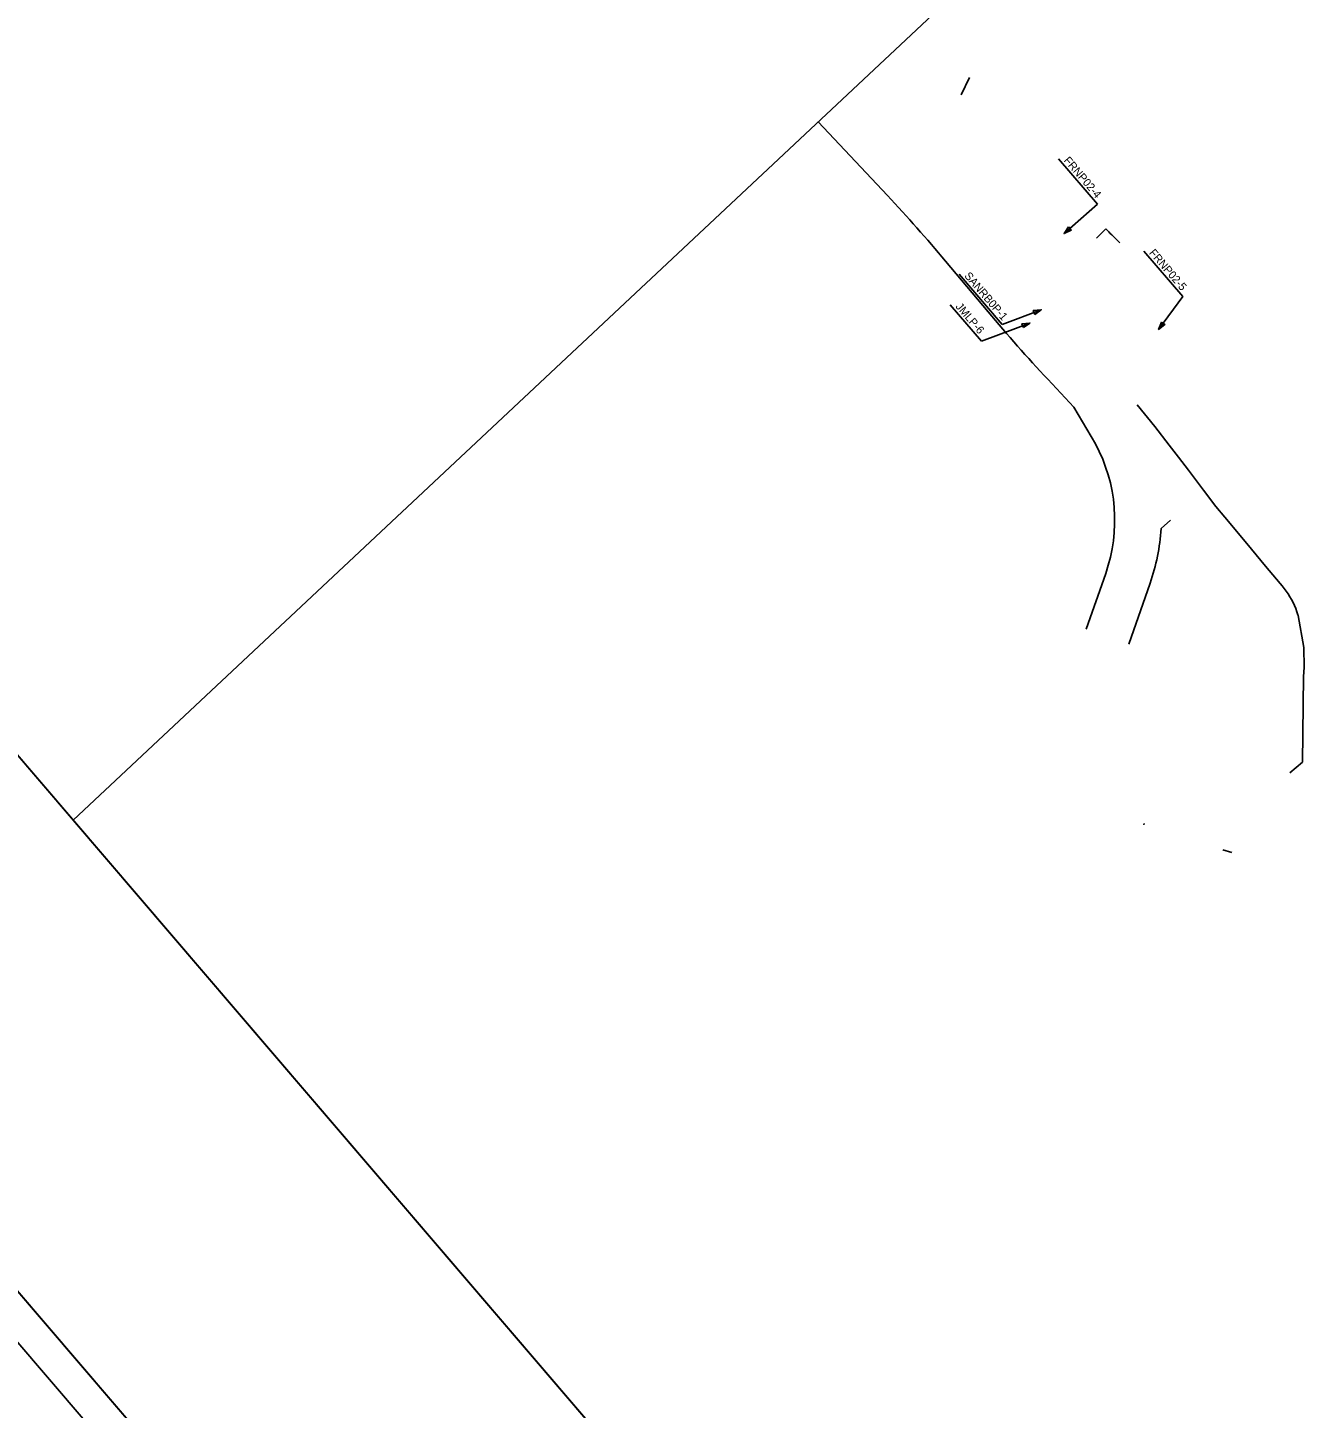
# Model space of a CAD drawing. Extents: x 1941897 to 1978064, y 805467 to 836604.
# Drawn here: x 1949186 to 1953062, y 821550 to 825709 of the extents above; entities that cross this region are included whole.
import ezdxf

# ---------------------------------------------------------------- set-up
doc = ezdxf.new("R2010")
doc.units = 0
for name, color, linetype in [('PIM_WALLS', 7, 'Continuous'), ('RD_EX_H20_TX', 7, 'Continuous'), ('RD_PD_RW', 7, 'Continuous'), ('RD_SHT_Bndy', 7, 'Continuous'), ('RD_SHT_IplotShp', 7, 'Continuous'), ('RD_TX_RoadID', 7, 'Continuous')]:
    doc.layers.add(name, color=color, linetype=linetype)

msp = doc.modelspace()

# ---------------------------------------------------------------- linework, layer by layer
at = {"layer": 'PIM_WALLS'}
for p in [(1953029.8, 823755.3), (1952988.4, 823464.4)]:
    msp.add_line(p, (1953026.7, 823496.9), dxfattribs=at)
msp.add_lwpolyline([(1952528.7, 824573), (1952582.1, 824507.9), (1952624.7, 824451.6), (1952652.5, 824415.9), (1952682.7, 824376.1), (1952728, 824316.6), (1952765.6, 824266.9), (1952792.3, 824234.7), (1952858.7, 824155.1), (1952915.2, 824087.1), (1952958.8, 824035.1), (1952965.3, 824027.6), (1952971.6, 824019.9), (1952977.5, 824011.8), (1952983.2, 824003.6), (1952988.5, 823995.1), (1952993.4, 823986.4), (1952998, 823977.5), (1953002.2, 823968.4), (1953006.1, 823959.2), (1953009.6, 823949.8), (1953012.7, 823940.4), (1953013.2, 823938.8), (1953030.3, 823842.2), (1953031.3, 823782), (1953029.8, 823755.3)], dxfattribs=at)
at = {"layer": 'RD_EX_H20_TX'}
for points in [[(1963151.2, 810860.3), (1959509.3, 815114.3), (1958096.8, 813905.1), (1957040.5, 814307.7), (1947588.1, 825348.6), (1952108, 829218.2), (1965848, 813169.1)], [(1963151.2, 810860.3), (1959509.3, 815114.3), (1958096.8, 813905.1), (1957040.5, 814307.7), (1947588.1, 825348.6), (1952108, 829218.2), (1965848, 813169.1)], [(1963151.2, 810860.3), (1959509.3, 815114.3), (1958096.8, 813905.1), (1957040.5, 814307.7), (1947588.1, 825348.6), (1952108, 829218.2), (1965848, 813169.1)], [(1963151.2, 810860.3), (1959509.3, 815114.3), (1958096.8, 813905.1), (1957040.5, 814307.7), (1949323.3, 823321.8), (1953668.8, 827395), (1965848, 813169.1)], [(1963151.2, 810860.3), (1959509.3, 815114.3), (1958096.8, 813905.1), (1957040.5, 814307.7), (1949323.3, 823321.8), (1953668.8, 827395), (1965848, 813169.1)], [(1963151.2, 810860.3), (1959509.3, 815114.3), (1958096.8, 813905.1), (1957040.5, 814307.7), (1949323.3, 823321.8), (1953668.8, 827395), (1965848, 813169.1)]]:
    msp.add_lwpolyline(points, close=True, dxfattribs=at)
at = {"layer": 'RD_PD_RW'}
for p, q in [((1952023.8, 825559.4), (1951998, 825506.4)), ((1951567.8, 825425.7), (1951776.3, 825203.4)), ((1952434.3, 825102.8), (1952405.8, 825074.7)), ((1952451.6, 825085.3), (1952476, 825060.8)), ((1952079.5, 824852.9), (1951951, 825006.2)), ((1952338, 824566), (1952259.2, 824650.2)), ((1952338, 824566), (1952402.9, 824455.3)), ((1952600.6, 824200.5), (1952628.5, 824226.1)), ((1952433.6, 824065.5), (1952374.9, 823897)), ((1952567.2, 824035.7), (1952503.3, 823852.3)), ((1952548, 823308.4), (1952549.6, 823312.5)), ((1952786.1, 823233.1), (1952813.4, 823224.4))]:
    msp.add_line(p, q, dxfattribs=at)
for centre, radius, start, end in [((1948323.1, 821966.5), 4733, 39.9581, 43.1477), ((1957344.4, 829950.6), 6900, 224.63423, 224.83885), ((1955810.1, 827978.6), 4867, 219.9581, 223.1477), ((1951974.7, 824225.5), 486, 340.7846, 28.228), ((1951979.9, 824240.4), 622, 340.7846, 356.3241)]:
    msp.add_arc(centre, radius, start, end, dxfattribs=at)
at = {"layer": 'RD_SHT_Bndy'}
for points in [[(1960707.9, 808409.5), (1943668.8, 828312), (1948986.3, 832864.4), (1966025.3, 812961.9)], [(1946512.2, 824990.8), (1956970, 812775.5), (1957767.7, 813458.3), (1947309.9, 825673.6)]]:
    msp.add_lwpolyline(points, close=True, dxfattribs=at)
at = {"layer": 'RD_SHT_IplotShp'}
msp.add_lwpolyline([(1960696.9, 808268.5), (1943527.9, 828323), (1948997.3, 833005.4), (1966166.3, 812950.9)], close=True, dxfattribs=at)
at = {"layer": 'RD_TX_RoadID'}
for p, q in [((1952408.5, 825177.6), (1952291.4, 825314.4)), ((1952665.6, 824899.2), (1952548.5, 825036)), ((1952121.4, 824815.4), (1951991.8, 824966.8)), ((1952059.1, 824764.9), (1951965.5, 824874.3))]:
    msp.add_line(p, q, dxfattribs=at)
for points in [[(1952408.5, 825177.6), (1952308.2, 825088.8)], [(1952665.6, 824899.2), (1952593.1, 824800.2)], [(1952059.1, 824764.9), (1952205.2, 824819.6)], [(1952121.4, 824815.4), (1952239.4, 824859.3)]]:
    msp.add_lwpolyline(points, dxfattribs=at)
for points in [[(1952321.5, 825108.8), (1952308.2, 825088.8), (1952329.7, 825099.5)], [(1952185.7, 824805.7), (1952205.2, 824819.6), (1952181.3, 824817.3)], [(1952219.8, 824845.4), (1952239.4, 824859.3), (1952215.5, 824857)], [(1952601.8, 824822.6), (1952593.1, 824800.2), (1952611.8, 824815.2)]]:
    msp.add_lwpolyline(points, close=True, dxfattribs=at)

# ---------------------------------------------------------------- texts
for s, p in [('FRNP02-4', (1952305.8, 825308.3)), ('FRNP02-5', (1952563, 825029.9)), ('SANRB0P-1', (1952006.3, 824960.7)), ('JMLP-6', (1951979.9, 824868.2))]:
    msp.add_text(s, height=24, rotation=310.5675, dxfattribs=at).set_placement(p)

doc.saveas('drawing.dxf')
